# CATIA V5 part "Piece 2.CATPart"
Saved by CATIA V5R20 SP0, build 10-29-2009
Part number: Piece 5
Bounding box of the stored display mesh (mm): x -10 to 0, y 247.019 to 313.034, z -147.191 to 123.241
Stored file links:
  C:\Users\Lambert\Desktop\IAO\Piece 2.CATPart
  C:\Users\Lambert\Desktop\IAO\Ass_Mon_IAO.CATProduct
  C:\Users\Lambert\Desktop\IAO\Piece5.CATPart
  C:\Users\Lambert\Desktop\IAO\Piece2.2.CATPart
  C:\Users\Lambert\Desktop\IAO\Piece 3.CATPart
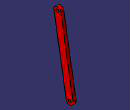
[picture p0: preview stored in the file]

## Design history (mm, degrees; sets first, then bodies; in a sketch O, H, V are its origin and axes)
Set1
  Line1 "Bielle 5": linked copy from another document
  DatumPoint1 "C": linked copy from another document
  DatumPoint2 "D": linked copy from another document
Body1 (main body)
  Sketch1 on yz-plane, origin (0, 0, 0), H (0, 1, 0), V (0, 0, 1)
    reference projected line E1 (301.0345, -135.197) -> (259.0188, 111.247) from edge of Line1
    construction line L1 (301.0345, -135.197) -> (259.0188, 111.247)
    point P3 (301.0345, -135.197)
    point P4 (259.0188, 111.247)
    line L2 (289.2052, -137.2138) -> (247.1895, 109.2303)
    line L3 (270.8482, 113.2638) -> (312.8638, -133.1803)
    arc A1 centre (259.0188, 111.247) radius 12 from (247.1895, 109.2303) to (270.8482, 113.2638) cw
    arc A2 centre (301.0345, -135.197) radius 12 from (312.8638, -133.1803) to (289.2052, -137.2138) cw
    reference projected point E2 (259.0188, 111.247) from DatumPoint1
    reference projected point E3 (301.0345, -135.197) from DatumPoint2
    distance L1 L2 = 12
    parallelism: L1 E1
    tangency: A1 L2, A2 L2, A1 L3, A2 L3
    coincidence: P4 E2, P3 E3
  Pad1: profile Sketch1, direction (-1, 0, 0), length 10
  Sketch2 on start face of Pad1, origin (0, 269.6969, 75.155), H (0, 1, 0), V (0, 0, 1)
    point P1 (-10.678, 36.092)
    reference projected point E1 (-10.678, 36.092) from DatumPoint1
    coincidence: P1 E1
  Hole1: placed by Sketch2, at (0, 259.0188, 111.247) direction (-1, 0, 0), diameter 10, depth 10
  Sketch3 on start face of Pad1, origin (0, 290.4971, -41.5827), H (0, 1, 0), V (0, 0, 1)
    point P1 (10.5374, -93.6143)
    reference projected point E1 (10.5374, -93.6143) from DatumPoint2
    coincidence: P1 E1
  Hole2: placed by Sketch3, at (0, 301.0345, -135.197) direction (-1, 0, 0), diameter 10, depth 10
